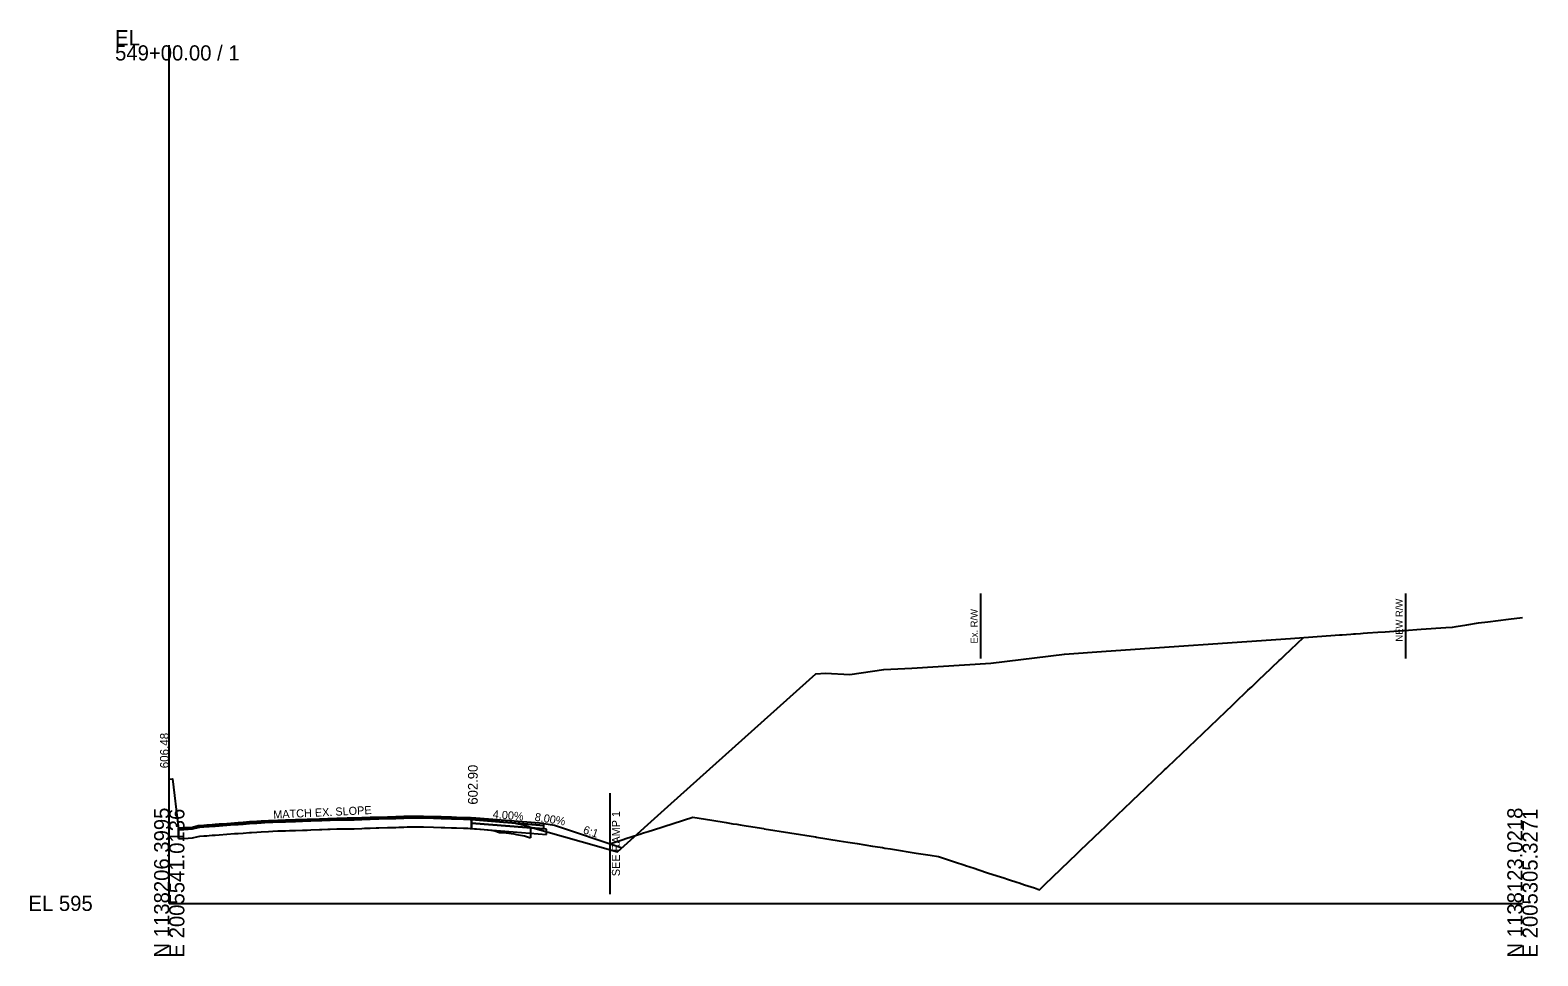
# Model space of a CAD drawing. Extents: x -201 to 2007062, y -213 to 1139737.
# Drawn here: x -25.7 to 252.8, y 5490.3 to 5661.3 of the extents above; entities that cross this region are included whole.
import ezdxf

# ---------------------------------------------------------------- set-up
doc = ezdxf.new("R2010")
doc.units = 0
for name, color, linetype in [('Default', 7, 'Continuous'), ('RD_DTM_Design_FG', 7, 'Continuous'), ('RD_GPK_XS_Cell', 7, 'Continuous'), ('RD_Sketch1', 7, 'Continuous'), ('RD_XS_Base', 7, 'Continuous'), ('RD_XS_EarthShd', 7, 'Continuous'), ('RD_XS_ExGround', 7, 'Continuous'), ('RD_XS_ExPaveRet', 7, 'Continuous'), ('RD_XS_ExRW', 7, 'Continuous'), ('RD_XS_NewRW', 7, 'Continuous'), ('RD_XS_PaveOvlay', 7, 'Continuous'), ('RD_XS_PaveShd', 7, 'Continuous'), ('RD_XS_SideStreet', 7, 'Continuous'), ('RD_XS_TieSlope', 7, 'Continuous'), ('RD_XS_TX_Elev_EX', 7, 'Continuous'), ('RD_XS_TX_Elev_PR', 7, 'Continuous'), ('RD_XS_TX_Slope', 7, 'Continuous')]:
    doc.layers.add(name, color=color, linetype=linetype)

msp = doc.modelspace()

# ---------------------------------------------------------------- linework, layer by layer
at = {"layer": 'RD_DTM_Design_FG'}
msp.add_lwpolyline([(81.41, 5511.02), (83.85, 5511.8), (84.37, 5511.97), (86.53, 5512.66), (86.93, 5512.79), (87.63, 5513.01), (88.47, 5513.28), (89.44, 5513.59), (96.73, 5515.91), (100.23, 5515.35), (102.91, 5514.92), (104.15, 5514.72), (104.86, 5514.61), (105.5, 5514.5), (106.59, 5514.33), (107.03, 5514.26), (109.84, 5513.81), (109.92, 5513.79), (119.41, 5512.27), (119.56, 5512.25), (123.74, 5511.58), (125.35, 5511.32), (127.12, 5511.04), (129.92, 5510.59), (130.43, 5510.51), (131.8, 5510.29), (132.22, 5510.22), (133.23, 5510.06), (133.59, 5510), (138, 5509.3), (140.6, 5508.88), (142.14, 5508.63), (144.71, 5507.79), (145.06, 5507.68), (147, 5507.04), (147.11, 5507.01), (148.72, 5506.48), (149.56, 5506.2), (151.19, 5505.67), (152.96, 5505.09), (154.17, 5504.7), (154.86, 5504.47), (155.21, 5504.36), (156.58, 5503.91), (157, 5503.77), (157.99, 5503.45), (159.83, 5502.85), (160.79, 5502.53), (161.79, 5503.49), (167.74, 5509.2), (168.37, 5509.81), (172.12, 5513.39), (172.89, 5514.13), (175.44, 5516.57), (176.21, 5517.31), (178.04, 5519.06), (180.27, 5521.19), (183.89, 5524.65), (184.23, 5524.97), (184.31, 5525.05), (184.34, 5525.08), (184.48, 5525.21), (190.92, 5531.36), (195.2, 5535.44), (196.41, 5536.6), (196.89, 5537.06), (199.29, 5539.35), (199.98, 5540.01), (201.44, 5541.4), (202.29, 5542.21), (205.05, 5544.84), (205.35, 5545.12), (206.05, 5545.79), (209.52, 5549.09)], dxfattribs=at)
at = {"layer": 'RD_GPK_XS_Cell'}
for q in [(0, 5658.49), (250, 5500)]:
    msp.add_line((0, 5500), q, dxfattribs=at)
at = {"layer": 'RD_XS_Base'}
for points in [[(69.19, 5514.41), (55.87, 5515.47)], [(55.87, 5515.47), (55.87, 5514.81)], [(69.69, 5513.71), (69.19, 5513.75), (55.87, 5514.81)], [(55.87, 5514.81), (55.87, 5513.81)], [(55.87, 5514.81), (69.19, 5513.75)], [(55.87, 5513.81), (69.69, 5512.71)], [(69.19, 5513.75), (69.19, 5514.41)], [(69.69, 5512.71), (69.69, 5513.71)]]:
    msp.add_lwpolyline(points, dxfattribs=at)
at = {"layer": 'RD_XS_EarthShd'}
msp.add_lwpolyline([(69.19, 5514.74), (71.19, 5514.42)], dxfattribs=at)
at = {"layer": 'RD_XS_ExGround'}
msp.add_lwpolyline([(0, 5522.95), (0.63, 5523.01), (1.64, 5514.24), (1.71, 5513.98), (2.67, 5513.99), (4.29, 5514.09), (5.35, 5514.38), (5.68, 5514.4), (6.38, 5514.46), (6.95, 5514.5), (7.38, 5514.53), (7.96, 5514.58), (8.48, 5514.62), (9.2, 5514.67), (10.62, 5514.76), (12.08, 5514.88), (12.74, 5514.92), (13.64, 5514.99), (14.86, 5515.1), (15.21, 5515.12), (16.19, 5515.17), (16.99, 5515.22), (18.35, 5515.3), (19.11, 5515.33), (20.06, 5515.37), (20.73, 5515.39), (21.48, 5515.41), (22.19, 5515.44), (23.35, 5515.47), (24.61, 5515.51), (25.47, 5515.55), (26.18, 5515.57), (27.75, 5515.63), (28.18, 5515.64), (29.31, 5515.68), (29.71, 5515.7), (30.94, 5515.74), (31.74, 5515.75), (32.17, 5515.76), (32.53, 5515.76), (32.9, 5515.77), (34.18, 5515.79), (35.58, 5515.85), (36.08, 5515.87), (37.15, 5515.9), (38.2, 5515.93), (38.72, 5515.94), (40.32, 5516), (41.85, 5516.03), (42.44, 5516.05), (43.32, 5516.09), (43.97, 5516.11), (44.32, 5516.13), (44.9, 5516.13), (46.97, 5516.13), (48.81, 5516.06), (50.25, 5516.03), (50.93, 5516.01), (52.17, 5515.96), (53.05, 5515.93), (54.39, 5515.89), (55.17, 5515.86), (55.62, 5515.83), (56.37, 5515.76), (56.77, 5515.74), (57.52, 5515.7), (58.17, 5515.63), (59.42, 5515.51), (60.13, 5515.42), (61.03, 5515.12), (61.54, 5515.07), (62.22, 5515.01), (63.66, 5514.85), (64.16, 5514.75), (65.66, 5514.45), (66.72, 5514.1), (76.12, 5511.42), (82.83, 5509.51), (92.7, 5518.46), (119.46, 5542.38), (121.22, 5542.54), (125.76, 5542.27), (132.02, 5543.21), (137.16, 5543.45), (151.81, 5544.34), (165.37, 5546.04), (173.07, 5546.57), (207.16, 5548.91), (215.41, 5549.53), (216.17, 5549.59), (216.69, 5549.62), (218.32, 5549.74), (218.76, 5549.77), (219.13, 5549.79), (220.05, 5549.86), (220.54, 5549.89), (221.39, 5549.95), (223.27, 5550.08), (224.62, 5550.18), (227.82, 5550.4), (228.13, 5550.42), (231.28, 5550.64), (235.82, 5550.95), (237.05, 5551.04), (237.76, 5551.17), (239.75, 5551.46), (241.9, 5551.79), (243.59, 5552), (247.39, 5552.49), (250, 5552.83)], dxfattribs=at)
at = {"layer": 'RD_XS_ExPaveRet'}
for p, q in [((55.87, 5514.81), (55.87, 5515.47)), ((55.87, 5515.47), (55.87, 5515.47)), ((1.71, 5511.98), (1.71, 5513.98)), ((1.71, 5513.65), (1.71, 5511.98)), ((4.29, 5512.09), (5.35, 5512.38)), ((4.29, 5512.09), (5.35, 5512.38)), ((5.35, 5512.38), (5.68, 5512.4)), ((5.35, 5512.38), (5.68, 5512.4)), ((5.68, 5512.4), (6.38, 5512.46)), ((5.68, 5512.4), (6.38, 5512.46)), ((6.38, 5512.46), (6.95, 5512.5)), ((6.38, 5512.46), (6.95, 5512.5)), ((6.95, 5512.5), (7.38, 5512.53)), ((6.95, 5512.5), (7.38, 5512.53)), ((7.38, 5512.53), (7.96, 5512.58)), ((7.38, 5512.53), (7.96, 5512.58)), ((7.96, 5512.58), (8.48, 5512.62)), ((7.96, 5512.58), (8.48, 5512.62)), ((8.48, 5512.62), (9.2, 5512.67)), ((8.48, 5512.62), (9.2, 5512.67)), ((9.2, 5512.67), (10.62, 5512.76)), ((9.2, 5512.67), (10.62, 5512.76)), ((10.62, 5512.76), (12.08, 5512.88)), ((10.62, 5512.76), (12.08, 5512.88)), ((12.08, 5512.88), (12.74, 5512.92)), ((12.08, 5512.88), (12.74, 5512.92)), ((12.74, 5512.92), (13.64, 5512.99)), ((12.74, 5512.92), (13.64, 5512.99)), ((13.64, 5512.99), (14.86, 5513.1)), ((13.64, 5512.99), (14.86, 5513.1)), ((14.86, 5513.1), (15.21, 5513.12)), ((14.86, 5513.1), (15.21, 5513.12)), ((15.21, 5513.12), (16.19, 5513.17)), ((15.21, 5513.12), (16.19, 5513.17)), ((16.19, 5513.17), (16.99, 5513.22)), ((16.19, 5513.17), (16.99, 5513.22)), ((16.99, 5513.22), (18.35, 5513.3)), ((16.99, 5513.22), (18.35, 5513.3)), ((18.35, 5513.3), (19.11, 5513.33)), ((18.35, 5513.3), (19.11, 5513.33)), ((19.11, 5513.33), (20.06, 5513.37)), ((19.11, 5513.33), (20.06, 5513.37)), ((20.06, 5513.37), (20.73, 5513.39)), ((20.06, 5513.37), (20.73, 5513.39)), ((20.73, 5513.39), (21.48, 5513.41)), ((20.73, 5513.39), (21.48, 5513.41)), ((21.48, 5513.41), (22.19, 5513.44)), ((21.48, 5513.41), (22.19, 5513.44)), ((22.19, 5513.44), (23.35, 5513.47)), ((22.19, 5513.44), (23.35, 5513.47)), ((23.35, 5513.47), (24.61, 5513.51)), ((23.35, 5513.47), (24.61, 5513.51)), ((24.61, 5513.51), (25.47, 5513.55)), ((24.61, 5513.51), (25.47, 5513.55)), ((25.47, 5513.55), (26.18, 5513.57)), ((25.47, 5513.55), (26.18, 5513.57)), ((26.18, 5513.57), (27.75, 5513.63)), ((26.18, 5513.57), (27.75, 5513.63)), ((27.75, 5513.63), (28.18, 5513.64)), ((27.75, 5513.63), (28.18, 5513.64)), ((28.18, 5513.64), (29.31, 5513.68)), ((28.18, 5513.64), (29.31, 5513.68)), ((29.31, 5513.68), (29.71, 5513.7)), ((29.31, 5513.68), (29.71, 5513.7)), ((29.71, 5513.7), (30.94, 5513.74)), ((29.71, 5513.7), (30.94, 5513.74)), ((30.94, 5513.74), (31.74, 5513.75)), ((30.94, 5513.74), (31.74, 5513.75)), ((31.74, 5513.75), (32.17, 5513.76)), ((31.74, 5513.75), (32.17, 5513.76)), ((32.17, 5513.76), (32.53, 5513.76)), ((32.17, 5513.76), (32.53, 5513.76)), ((32.53, 5513.76), (32.9, 5513.77)), ((32.53, 5513.76), (32.9, 5513.77)), ((32.9, 5513.77), (34.18, 5513.79)), ((32.9, 5513.77), (34.18, 5513.79)), ((34.18, 5513.79), (35.58, 5513.85)), ((34.18, 5513.79), (35.58, 5513.85)), ((35.58, 5513.85), (36.08, 5513.87)), ((35.58, 5513.85), (36.08, 5513.87)), ((36.08, 5513.87), (37.15, 5513.9)), ((36.08, 5513.87), (37.15, 5513.9)), ((37.15, 5513.9), (38.2, 5513.93)), ((37.15, 5513.9), (38.2, 5513.93)), ((38.2, 5513.93), (38.72, 5513.94)), ((38.2, 5513.93), (38.72, 5513.94)), ((38.72, 5513.94), (40.32, 5514)), ((38.72, 5513.94), (40.32, 5514)), ((40.32, 5514), (41.85, 5514.03)), ((40.32, 5514), (41.85, 5514.03)), ((41.85, 5514.03), (42.44, 5514.05)), ((41.85, 5514.03), (42.44, 5514.05)), ((42.44, 5514.05), (43.32, 5514.09)), ((42.44, 5514.05), (43.32, 5514.09)), ((43.32, 5514.09), (43.97, 5514.11)), ((43.32, 5514.09), (43.97, 5514.11)), ((43.97, 5514.11), (44.32, 5514.13)), ((43.97, 5514.11), (44.32, 5514.13)), ((44.32, 5514.13), (44.9, 5514.13)), ((44.32, 5514.13), (44.9, 5514.13)), ((44.9, 5514.13), (46.97, 5514.13)), ((44.9, 5514.13), (46.97, 5514.13)), ((46.97, 5514.13), (48.81, 5514.06)), ((46.97, 5514.13), (48.81, 5514.06)), ((48.81, 5514.06), (50.25, 5514.03)), ((48.81, 5514.06), (50.25, 5514.03)), ((50.25, 5514.03), (50.93, 5514.01)), ((50.25, 5514.03), (50.93, 5514.01)), ((50.93, 5514.01), (52.17, 5513.96)), ((50.93, 5514.01), (52.17, 5513.96)), ((52.17, 5513.96), (53.05, 5513.93)), ((52.17, 5513.96), (53.05, 5513.93)), ((53.05, 5513.93), (54.39, 5513.89)), ((53.05, 5513.93), (54.39, 5513.89)), ((54.39, 5513.89), (55.17, 5513.86)), ((54.39, 5513.89), (55.17, 5513.86)), ((55.17, 5513.86), (55.62, 5513.83)), ((55.17, 5513.86), (55.62, 5513.83)), ((55.62, 5513.83), (56.37, 5513.76)), ((55.62, 5513.83), (55.87, 5513.81)), ((55.87, 5513.81), (55.87, 5514.81)), ((55.87, 5513.81), (55.87, 5513.81)), ((55.87, 5513.81), (55.87, 5513.81)), ((56.37, 5513.76), (56.77, 5513.74)), ((56.77, 5513.74), (57.52, 5513.7)), ((57.52, 5513.7), (58.17, 5513.63)), ((58.17, 5513.63), (59.42, 5513.51)), ((59.42, 5513.51), (60.13, 5513.42)), ((60.13, 5513.42), (61.03, 5513.12)), ((61.03, 5513.12), (61.54, 5513.07)), ((61.54, 5513.07), (62.22, 5513.01)), ((62.22, 5513.01), (63.66, 5512.85)), ((63.66, 5512.85), (64.16, 5512.75)), ((64.16, 5512.75), (65.66, 5512.45)), ((65.66, 5512.45), (66.72, 5512.1)), ((66.72, 5514.1), (66.72, 5512.1)), ((1.71, 5511.98), (2.67, 5511.99)), ((1.71, 5511.98), (2.67, 5511.99)), ((2.67, 5511.99), (4.29, 5512.09)), ((2.67, 5511.99), (4.29, 5512.09))]:
    msp.add_line(p, q, dxfattribs=at)
msp.add_lwpolyline([(55.87, 5515.47), (55.62, 5515.5), (55.17, 5515.53), (54.39, 5515.55), (53.05, 5515.6), (52.17, 5515.63), (50.93, 5515.68), (50.25, 5515.69), (48.81, 5515.73), (46.97, 5515.79), (44.9, 5515.8), (44.32, 5515.8), (43.97, 5515.78), (43.32, 5515.76), (42.44, 5515.72), (41.85, 5515.7), (40.32, 5515.67), (38.72, 5515.61), (38.2, 5515.6), (37.15, 5515.57), (36.08, 5515.53), (35.58, 5515.52), (34.18, 5515.46), (32.9, 5515.44), (32.53, 5515.43), (32.17, 5515.43), (31.74, 5515.42), (30.94, 5515.41), (29.71, 5515.37), (29.31, 5515.35), (28.18, 5515.31), (27.75, 5515.3), (26.18, 5515.24), (25.47, 5515.22), (24.61, 5515.18), (23.35, 5515.14), (22.19, 5515.1), (21.48, 5515.08), (20.73, 5515.06), (20.06, 5515.04), (19.11, 5515), (18.35, 5514.97), (16.99, 5514.89), (16.19, 5514.84), (15.21, 5514.79), (14.86, 5514.76), (13.64, 5514.65), (12.74, 5514.59), (12.08, 5514.54), (10.62, 5514.43), (9.2, 5514.33), (8.48, 5514.28), (7.96, 5514.24), (7.38, 5514.2), (6.95, 5514.17), (6.38, 5514.13), (5.68, 5514.07), (5.35, 5514.04), (4.29, 5513.76), (2.67, 5513.65), (1.71, 5513.65)], dxfattribs=at)
at = {"layer": 'RD_XS_ExRW'}
msp.add_line((149.85, 5557.23), (149.85, 5545.23), dxfattribs=at)
at = {"layer": 'RD_XS_NewRW'}
msp.add_line((228.42, 5557.23), (228.42, 5545.23), dxfattribs=at)
at = {"layer": 'RD_XS_PaveOvlay'}
for points in [[(1.71, 5513.98), (2.67, 5513.99), (4.29, 5514.09), (5.35, 5514.38), (5.68, 5514.4), (6.38, 5514.46), (6.95, 5514.5), (7.38, 5514.53), (7.96, 5514.58), (8.48, 5514.62), (9.2, 5514.67), (10.62, 5514.76), (12.08, 5514.88), (12.74, 5514.92), (13.64, 5514.99), (14.86, 5515.1), (15.21, 5515.12), (16.19, 5515.17), (16.99, 5515.22), (18.35, 5515.3), (19.11, 5515.33), (20.06, 5515.37), (20.73, 5515.39), (21.48, 5515.41), (22.19, 5515.44), (23.35, 5515.47), (24.61, 5515.51), (25.47, 5515.55), (26.18, 5515.57), (27.75, 5515.63), (28.18, 5515.64), (29.31, 5515.68), (29.71, 5515.7), (30.94, 5515.74), (31.74, 5515.75), (32.17, 5515.76), (32.53, 5515.76), (32.9, 5515.77), (34.18, 5515.79), (35.58, 5515.85), (36.08, 5515.87), (37.15, 5515.9), (38.2, 5515.93), (38.72, 5515.94), (40.32, 5516), (41.85, 5516.03), (42.44, 5516.05), (43.32, 5516.09), (43.97, 5516.11), (44.32, 5516.13), (44.9, 5516.13), (46.97, 5516.13), (48.81, 5516.06), (50.25, 5516.03), (50.93, 5516.01), (52.17, 5515.96), (53.05, 5515.93), (54.39, 5515.89), (55.17, 5515.86), (55.62, 5515.83), (55.87, 5515.81)], [(1.71, 5513.65), (2.67, 5513.65), (4.29, 5513.76), (5.35, 5514.04), (5.68, 5514.07), (6.38, 5514.13), (6.95, 5514.17), (7.38, 5514.2), (7.96, 5514.24), (8.48, 5514.28), (9.2, 5514.33), (10.62, 5514.43), (12.08, 5514.54), (12.74, 5514.59), (13.64, 5514.65), (14.86, 5514.76), (15.21, 5514.79), (16.19, 5514.84), (16.99, 5514.89), (18.35, 5514.97), (19.11, 5515), (20.06, 5515.04), (20.73, 5515.06), (21.48, 5515.08), (22.19, 5515.1), (23.35, 5515.14), (24.61, 5515.18), (25.47, 5515.22), (26.18, 5515.24), (27.75, 5515.3), (28.18, 5515.31), (29.31, 5515.35), (29.71, 5515.37), (30.94, 5515.41), (31.74, 5515.42), (32.17, 5515.43), (32.53, 5515.43), (32.9, 5515.44), (34.18, 5515.46), (35.58, 5515.52), (36.08, 5515.53), (37.15, 5515.57), (38.2, 5515.6), (38.72, 5515.61), (40.32, 5515.67), (41.85, 5515.7), (42.44, 5515.72), (43.32, 5515.76), (43.97, 5515.78), (44.32, 5515.8), (44.9, 5515.8), (46.97, 5515.79), (48.81, 5515.73), (50.25, 5515.69), (50.93, 5515.68), (52.17, 5515.63), (53.05, 5515.6), (54.39, 5515.55), (55.17, 5515.53), (55.62, 5515.5), (55.87, 5515.47)]]:
    msp.add_lwpolyline(points, dxfattribs=at)
at = {"layer": 'RD_XS_PaveShd'}
for points in [[(69.19, 5514.74), (55.87, 5515.81)], [(55.87, 5515.81), (55.87, 5515.47)], [(55.87, 5515.47), (69.19, 5514.41)], [(69.19, 5514.41), (69.19, 5514.74)]]:
    msp.add_lwpolyline(points, dxfattribs=at)
at = {"layer": 'RD_XS_SideStreet'}
msp.add_line((81.4, 5520.36), (81.4, 5501.68), dxfattribs=at)
at = {"layer": 'RD_XS_TieSlope'}
msp.add_lwpolyline([(71.19, 5514.42), (83.66, 5510.27)], dxfattribs=at)

# ---------------------------------------------------------------- texts
at = {"layer": 'Default'}
msp.add_text('-', height=0.0001, dxfattribs=at).set_placement((0, 5500))
at = {"layer": 'RD_GPK_XS_Cell'}
for s, p in [('EL', (-10, 5658.49)), ('549+00.00 / 1', (-10, 5655.69)), ('EL 595', (-26, 5498.6))]:
    msp.add_text(s, height=2.8, dxfattribs=at).set_placement(p)
for s, p in [('N 1138206.3995', (0, 5490)), ('E 2005541.0136', (2.8, 5490)), ('N 1138123.0218', (250, 5490)), ('E 2005305.3271', (252.8, 5490))]:
    msp.add_text(s, height=2.8, rotation=90, dxfattribs=at).set_placement(p)
at = {"layer": 'RD_Sketch1'}
for s, p in [('Exterior Boundary', (55.31, 5515.76)), ('EP_X_R', (55.6, 5515.76)), ('EP_X1', (55.66, 5515.42)), ('549+00.00', (60.6, 5515.35)), ('EP_X2', (55.65, 5514.76)), ('EP_X3', (55.65, 5513.76)), ('ESP1_R', (68.93, 5514.36)), ('ESP2_R', (68.93, 5513.7)), ('ESP_R', (68.97, 5514.69)), ('ESP4_R', (69.43, 5513.66)), ('ESP3_R', (69.43, 5512.66)), ('ES_R', (71.01, 5514.37)), ('Exterior Boundary', (83.11, 5510.22)), ('CLZ_R', (83.44, 5510.22))]:
    msp.add_text(s, height=0.05, dxfattribs=at).set_placement(p)
at = {"layer": 'RD_XS_ExRW'}
msp.add_text('Ex. R/W ', height=1.3, rotation=90, dxfattribs=at).set_placement((149.35, 5547.99))
at = {"layer": 'RD_XS_NewRW'}
msp.add_text('NEW R/W ', height=1.3, rotation=90, dxfattribs=at).set_placement((227.88, 5548.35))
at = {"layer": 'RD_XS_SideStreet'}
msp.add_text('SEE RAMP 1', height=1.5, rotation=90, dxfattribs=at).set_placement((83.28, 5505.02))
at = {"layer": 'RD_XS_TX_Elev_EX'}
msp.add_text('606.48', height=1.6, rotation=90, dxfattribs=at).set_placement((-0.1, 5524.95))
at = {"layer": 'RD_XS_TX_Elev_PR'}
msp.add_text('602.90', height=1.8, rotation=90, dxfattribs=at).set_placement((56.99, 5518.24))
at = {"layer": 'RD_XS_TX_Slope'}
for s, rotation, p in [('MATCH EX. SLOPE', 2.7318, (19.26, 5515.64)), ('4.00%', 355.4366, (59.73, 5515.75)), ('8.00%', 350.9215, (67.44, 5515.28)), ('6:1', 341.5788, (76.34, 5512.97))]:
    msp.add_text(s, height=1.5, rotation=rotation, dxfattribs=at).set_placement(p)

doc.saveas('drawing.dxf')
